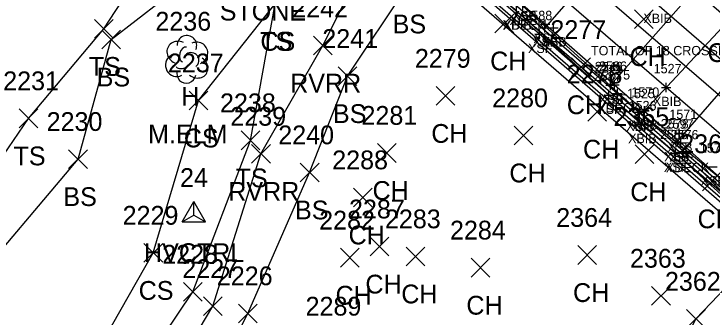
# Model space of a CAD drawing. Extents: x 1459992 to 1461532, y 647785 to 648535.
# Drawn here: x 1461256.6 to 1461331.1, y 648158.1 to 648190.4 of the extents above; entities that cross this region are included whole.
import ezdxf

# ---------------------------------------------------------------- set-up
doc = ezdxf.new("R2010")
doc.units = 0
for name, color, linetype in [('B_A', 7, 'Continuous'), ('B_C', 7, 'Continuous'), ('B_I', 7, 'Continuous'), ('B_TIC', 7, 'Continuous'), ('BB', 7, 'Continuous'), ('BDEFAULT', 7, 'Continuous'), ('BELB', 7, 'Continuous'), ('C_A', 7, 'Continuous'), ('C_I', 7, 'Continuous'), ('CPSM', 7, 'Continuous'), ('L_A', 7, 'Continuous'), ('L_C', 7, 'Continuous'), ('L_I', 7, 'Continuous'), ('L_TIC', 7, 'Continuous'), ('LAWE', 7, 'Continuous'), ('LELB', 7, 'Continuous'), ('LTD', 7, 'Continuous')]:
    doc.layers.add(name, color=color, linetype=linetype)

msp = doc.modelspace()

# ---------------------------------------------------------------- linework, layer by layer
at = {"layer": 'B_TIC'}
for p, q in [((1461313.281, 648189.283), (1461313.356, 648189.283)), ((1461313.247, 648188.887), (1461313.322, 648188.887)), ((1461314.158, 648188.899), (1461314.233, 648188.899)), ((1461312.687, 648188.203), (1461312.762, 648188.203)), ((1461320.233, 648182.764), (1461320.308, 648182.764)), ((1461320.683, 648182.814), (1461320.759, 648182.814)), ((1461326.197, 648182.545), (1461326.272, 648182.545)), ((1461320.992, 648181.882), (1461321.067, 648181.882)), ((1461320.086, 648181.72), (1461320.161, 648181.72)), ((1461323.356, 648179.892), (1461323.432, 648179.892)), ((1461323.863, 648180.043), (1461323.938, 648180.043)), ((1461323.551, 648178.602), (1461323.627, 648178.602)), ((1461327.584, 648177.68), (1461327.66, 648177.68)), ((1461327.237, 648176.673), (1461327.312, 648176.673)), ((1461327.752, 648176.637), (1461327.827, 648176.637)), ((1461327.176, 648175.537), (1461327.252, 648175.537)), ((1461328.315, 648175.511), (1461328.391, 648175.511))]:
    msp.add_line(p, q, dxfattribs=at)
for points in [[(1461310.231, 648190.193), (1461310.231, 648191.193)], [(1461310.883, 648190.176), (1461310.883, 648191.176)], [(1461312.777, 648189.283), (1461313.777, 648189.283)], [(1461313.243, 648188.387), (1461313.243, 648189.387)], [(1461313.277, 648188.783), (1461313.277, 648189.783)], [(1461314.154, 648188.399), (1461314.154, 648189.399)], [(1461312.683, 648187.703), (1461312.683, 648188.703)], [(1461312.743, 648188.887), (1461313.743, 648188.887)], [(1461313.654, 648188.899), (1461314.654, 648188.899)], [(1461312.183, 648188.203), (1461313.183, 648188.203)], [(1461320.229, 648182.264), (1461320.229, 648183.264)], [(1461320.68, 648182.314), (1461320.68, 648183.314)], [(1461319.729, 648182.764), (1461320.729, 648182.764)], [(1461320.18, 648182.814), (1461321.18, 648182.814)], [(1461325.694, 648182.545), (1461326.694, 648182.545)], [(1461326.194, 648182.045), (1461326.194, 648183.045)], [(1461320.082, 648181.22), (1461320.082, 648182.22)], [(1461320.488, 648181.882), (1461321.488, 648181.882)], [(1461320.988, 648181.382), (1461320.988, 648182.382)], [(1461319.582, 648181.72), (1461320.582, 648181.72)], [(1461323.353, 648179.392), (1461323.353, 648180.392)], [(1461323.859, 648179.543), (1461323.859, 648180.543)], [(1461322.853, 648179.892), (1461323.853, 648179.892)], [(1461323.359, 648180.043), (1461324.359, 648180.043)], [(1461323.548, 648178.102), (1461323.548, 648179.102)], [(1461323.048, 648178.602), (1461324.048, 648178.602)], [(1461327.581, 648177.18), (1461327.581, 648178.18)], [(1461327.081, 648177.68), (1461328.081, 648177.68)], [(1461326.733, 648176.673), (1461327.733, 648176.673)], [(1461327.233, 648176.173), (1461327.233, 648177.173)], [(1461327.248, 648176.637), (1461328.248, 648176.637)], [(1461327.748, 648176.137), (1461327.748, 648177.137)], [(1461327.173, 648175.037), (1461327.173, 648176.037)], [(1461328.312, 648175.011), (1461328.312, 648176.011)], [(1461326.673, 648175.537), (1461327.673, 648175.537)], [(1461327.812, 648175.511), (1461328.812, 648175.511)], [(1461330.62, 648174.098), (1461331.62, 648174.098)]]:
    msp.add_lwpolyline(points, dxfattribs=at)
at = {"layer": 'BB'}
for points in [[(1461357.803, 648164.521), (1461346.033, 648173.409), (1461325.183, 648191.393), (1461321.182, 648194.832), (1461311.295, 648203.276), (1461301.649, 648211.621), (1461295.127, 648216.651)], [(1461285.13, 648212.323), (1461354.607, 648152.433)], [(1461353.847, 648159.998), (1461342.222, 648168.764), (1461326.194, 648182.545), (1461313.236, 648193.724), (1461305.462, 648200.447), (1461296.007, 648208.646)], [(1461344.989, 648161.367), (1461336.505, 648169.128), (1461323.353, 648179.892), (1461310.889, 648191.178), (1461301.256, 648198.966), (1461293.739, 648205.641), (1461291.431, 648207.823)], [(1461344.755, 648160.272), (1461335.81, 648168.189), (1461323.548, 648178.602), (1461310.231, 648190.693), (1461300.415, 648198.699), (1461293.114, 648204.901), (1461290.791, 648207.096)], [(1461322.069, 648198.982), (1461313.243, 648188.887)], [(1461320.229, 648182.764), (1461329.099, 648192.816)], [(1461323.859, 648180.043), (1461332.641, 648189.458)], [(1461336.035, 648186.774), (1461327.233, 648176.673)]]:
    msp.add_lwpolyline(points, dxfattribs=at)
at = {"layer": 'BDEFAULT'}
for points in [[(1461360.363, 648157.144), (1461288.944, 648218.654)], [(1461354.171, 648150.001), (1461282.953, 648211.596)], [(1461353.858, 648151.867), (1461350.867, 648153.898), (1461289.362, 648207.393), (1461287.217, 648209.127), (1461285.016, 648211.458)], [(1461353.858, 648151.867), (1461285.016, 648211.458)], [(1461350.543, 648155.26), (1461340.882, 648163.524), (1461333.523, 648169.773), (1461327.173, 648175.537), (1461320.082, 648181.72), (1461312.683, 648188.203), (1461305.743, 648194.222), (1461298.88, 648200.08), (1461289.091, 648208.417)], [(1461292.894, 648206.723), (1461299.511, 648201.164), (1461306.374, 648195.289), (1461313.277, 648189.283), (1461320.68, 648182.814), (1461327.748, 648176.637), (1461334.696, 648170.496), (1461341.563, 648164.557), (1461348.45, 648158.681)]]:
    msp.add_lwpolyline(points, dxfattribs=at)
at = {"layer": 'BELB'}
msp.add_lwpolyline([(1461362.021, 648164.506), (1461356.918, 648168.766), (1461356.744, 648168.633), (1461346.243, 648178.153), (1461335.102, 648187.79), (1461324.925, 648196.655), (1461312.315, 648207.599), (1461296.583, 648221.232), (1461287.57, 648210.913), (1461301.391, 648198.959), (1461310.883, 648190.676), (1461320.988, 648181.882), (1461328.312, 648175.511), (1461338.631, 648166.593)], dxfattribs=at)
at = {"layer": 'CPSM'}
for p, q in [((1461274.537, 648168.22), (1461275.787, 648170.386)), ((1461277.037, 648168.22), (1461275.787, 648170.386)), ((1461275.788, 648168.942), (1461275.787, 648170.386)), ((1461274.537, 648168.22), (1461275.788, 648168.942)), ((1461275.788, 648168.942), (1461275.788, 648168.942)), ((1461275.788, 648168.942), (1461277.037, 648168.22)), ((1461274.537, 648168.22), (1461277.037, 648168.22))]:
    msp.add_line(p, q, dxfattribs=at)
at = {"layer": 'L_TIC'}
for points in [[(1461322.786, 648188.818), (1461324.786, 648190.818)], [(1461324.786, 648188.818), (1461322.786, 648190.818)], [(1461307.915, 648188.354), (1461309.915, 648190.354)], [(1461309.915, 648188.354), (1461307.915, 648190.354)], [(1461265.186, 648187.777), (1461267.186, 648189.777)], [(1461267.186, 648187.777), (1461265.186, 648189.777)], [(1461265.99, 648186.645), (1461267.99, 648188.645)], [(1461267.99, 648186.645), (1461265.99, 648188.645)], [(1461288.558, 648185.996), (1461290.558, 648187.996)], [(1461290.558, 648185.996), (1461288.558, 648187.996)], [(1461316.092, 648183.694), (1461318.092, 648185.694)], [(1461318.092, 648183.694), (1461316.092, 648185.694)], [(1461291.193, 648182.75), (1461293.193, 648184.75)], [(1461293.193, 648182.75), (1461291.193, 648184.75)], [(1461301.64, 648180.64), (1461303.64, 648182.64)], [(1461303.64, 648180.64), (1461301.64, 648182.64)], [(1461275.289, 648180.15), (1461277.289, 648182.15)], [(1461277.289, 648180.15), (1461275.289, 648182.15)], [(1461317.822, 648178.961), (1461319.822, 648180.961)], [(1461319.822, 648178.961), (1461317.822, 648180.961)], [(1461257.154, 648178.244), (1461259.154, 648180.244)], [(1461259.154, 648178.244), (1461257.154, 648180.244)], [(1461309.967, 648176.427), (1461311.967, 648178.427)], [(1461311.967, 648176.427), (1461309.967, 648178.427)], [(1461280.846, 648175.9), (1461282.846, 648177.9)], [(1461282.846, 648175.9), (1461280.846, 648177.9)], [(1461295.371, 648174.562), (1461297.371, 648176.562)], [(1461297.371, 648174.562), (1461295.371, 648176.562)], [(1461262.44, 648173.908), (1461264.44, 648175.908)], [(1461264.44, 648173.908), (1461262.44, 648175.908)], [(1461281.957, 648174.462), (1461283.957, 648176.462)], [(1461283.957, 648174.462), (1461281.957, 648176.462)], [(1461322.866, 648174.422), (1461324.866, 648176.422)], [(1461324.866, 648174.422), (1461322.866, 648176.422)], [(1461287.148, 648172.487), (1461289.148, 648174.487)], [(1461289.148, 648172.487), (1461287.148, 648174.487)], [(1461330.042, 648171.541), (1461332.042, 648173.541)], [(1461332.042, 648171.541), (1461330.042, 648173.541)], [(1461292.817, 648169.822), (1461294.817, 648171.822)], [(1461294.817, 648169.822), (1461292.817, 648171.822)], [(1461294.61, 648164.59), (1461296.61, 648166.59)], [(1461296.61, 648164.59), (1461294.61, 648166.59)], [(1461270.471, 648163.918), (1461272.471, 648165.918)], [(1461272.471, 648163.918), (1461270.471, 648165.918)], [(1461291.423, 648163.407), (1461293.423, 648165.407)], [(1461293.423, 648163.407), (1461291.423, 648165.407)], [(1461298.439, 648163.54), (1461300.439, 648165.54)], [(1461300.439, 648163.54), (1461298.439, 648165.54)], [(1461316.757, 648163.688), (1461318.757, 648165.688)], [(1461318.757, 648163.688), (1461316.757, 648165.688)], [(1461305.38, 648162.342), (1461307.38, 648164.342)], [(1461307.38, 648162.342), (1461305.38, 648164.342)], [(1461274.686, 648159.772), (1461276.686, 648161.772)], [(1461276.686, 648159.772), (1461274.686, 648161.772)], [(1461324.629, 648159.341), (1461326.629, 648161.341)], [(1461326.629, 648159.341), (1461324.629, 648161.341)], [(1461276.829, 648158.24), (1461278.829, 648160.24)], [(1461278.829, 648158.24), (1461276.829, 648160.24)], [(1461280.565, 648157.473), (1461282.565, 648159.473)], [(1461282.565, 648157.473), (1461280.565, 648159.473)], [(1461328.36, 648156.887), (1461330.36, 648158.887)], [(1461330.36, 648156.887), (1461328.36, 648158.887)]]:
    msp.add_lwpolyline(points, dxfattribs=at)
at = {"layer": 'LAWE'}
msp.add_lwpolyline([(1461175.582, 648047.692), (1461190.072, 648060.795), (1461210.579, 648076.7), (1461225.386, 648087.992), (1461242.999, 648102.806), (1461257.751, 648117.016), (1461268.272, 648143.142), (1461277.829, 648159.24), (1461282.957, 648175.462), (1461289.558, 648186.996), (1461293.87, 648195.588), (1461292.337, 648203.444)], dxfattribs=at)
at = {"layer": 'LELB'}
for points in [[(1461216.735, 648025.379), (1461232.531, 648043.682), (1461249.111, 648052.696), (1461265.41, 648068.573), (1461273.176, 648074.771), (1461285.769, 648090.042), (1461304.003, 648110.191), (1461314.102, 648129.874), (1461321.787, 648141.876), (1461329.36, 648157.887), (1461338.075, 648167.022), (1461343.94, 648182.363), (1461347.487, 648202.693), (1461348.844, 648222.98), (1461349.522, 648245.94), (1461349.946, 648262.877), (1461353.497, 648277.365), (1461366.77, 648299.226), (1461380.277, 648319.065), (1461391.623, 648332.953), (1461418.599, 648338.961), (1461441.306, 648340.652), (1461465.695, 648340.733), (1461485.923, 648346.235)], [(1461181.212, 648043.592), (1461191.79, 648059.054), (1461212.855, 648073.874), (1461227.371, 648085.596), (1461246.178, 648099.024), (1461260.669, 648114.058), (1461272.144, 648139.82), (1461281.565, 648158.473), (1461288.148, 648173.487), (1461292.193, 648183.75), (1461298.563, 648193.295), (1461300.86, 648204.122), (1461298.63, 648210.737)], [(1461127.841, 648072.025), (1461157.366, 648076.315), (1461166.908, 648084.021), (1461183.556, 648102.817), (1461209.905, 648116.903), (1461222.502, 648127.212), (1461235.952, 648145.681), (1461248.534, 648165.182), (1461258.154, 648179.244), (1461266.186, 648188.777), (1461271.994, 648197.654)], [(1461133.589, 648067.118), (1461157.379, 648067.438), (1461176.46, 648078.839), (1461190.117, 648095.99), (1461212.044, 648111.684), (1461225.88, 648123.016), (1461241.312, 648138.966), (1461251.31, 648160.567), (1461263.44, 648174.908), (1461266.99, 648187.645), (1461277.642, 648195.929)], [(1461171.661, 648050.372), (1461189.066, 648062.585), (1461207.829, 648079.497), (1461223.93, 648090.745), (1461240.199, 648105.174), (1461254.637, 648120.348), (1461266.382, 648146.936), (1461275.686, 648160.772), (1461281.846, 648176.9), (1461284.459, 648191.448), (1461287.846, 648196.16)], [(1461162.415, 648057.492), (1461184.81, 648068.652), (1461202.033, 648084.354), (1461220.873, 648096.789), (1461234.917, 648111.93), (1461250.129, 648125.473), (1461262.717, 648149.553), (1461271.471, 648164.918), (1461276.289, 648181.15), (1461284.459, 648191.448)]]:
    msp.add_lwpolyline(points, dxfattribs=at)
at = {"layer": 'LTD'}
msp.add_line((1461275.01, 648185.587), (1461275.01, 648185.587), dxfattribs=at)
msp.add_line((1461275.01, 648185.587), (1461275.01, 648185.587), dxfattribs=at)
msp.add_arc((1461275.057, 648187.021), 1.047, 335.52715, 180.95627, dxfattribs=at)
for centre, major_axis, ratio, start_param, end_param in [((1461274.218, 648186.254), (1.21, -0.512), 0.895232, 1.570796, 4.712389), ((1461276.052, 648186.171), (-1.141, -0.483), 0.949671, 1.570796, 4.712389), ((1461274.802, 648186.045), (-0.208, -0.792), 0.645439, 3.141593, 6.283185), ((1461275.51, 648185.42), (-0.5, 0.667), 0.989748, 3.141593, 6.283185), ((1461273.927, 648184.879), (0.584, -1.042), 0.959034, 3.141593, 6.283185), ((1461276.01, 648184.754), (-1.09, 0.792), 0.841452, 1.570796, 4.712389), ((1461274.552, 648184.837), (-0.625, -0.083), 0.423636, 0, 3.141593), ((1461275.01, 648184.087), (0.265, 1.061), 0.942809, 1.570796, 4.712389)]:
    msp.add_ellipse(centre, major_axis=major_axis, ratio=ratio, start_param=start_param, end_param=end_param, dxfattribs=at)

# ---------------------------------------------------------------- texts
at = {"layer": 'B_A'}
for s, p in [('XSB', (1461309.705, 648189.688)), ('XBIB', (1461309.46, 648189.178)), ('XBIB', (1461323.754, 648189.393)), ('XDECK', (1461308.725, 648188.676)), ('XBIB', (1461308.802, 648188.693)), ('XSB', (1461311.979, 648186.887)), ('XSF', (1461312.037, 648187.283)), ('XSB', (1461312.891, 648186.899)), ('XSF', (1461311.443, 648186.203)), ('XSB', (1461318.965, 648180.764)), ('XSF', (1461319.44, 648180.814)), ('XBIB', (1461324.764, 648180.545)), ('XDECK', (1461318.831, 648179.882)), ('XSF', (1461318.842, 648179.72)), ('XBIB', (1461321.923, 648177.892)), ('XSB', (1461322.595, 648178.043)), ('XBIB', (1461322.119, 648176.602)), ('XSB', (1461326.317, 648175.68)), ('XSB', (1461325.97, 648174.673)), ('XSF', (1461326.508, 648174.637)), ('XSF', (1461325.932, 648173.537)), ('XDECK', (1461326.154, 648173.511)), ('XSB', (1461329.856, 648172.098))]:
    msp.add_text(s, height=1, dxfattribs=at).set_placement(p)
at = {"layer": 'B_C'}
msp.add_text('TOTAL OF 18 CROSSBEAM & WE WHAT', height=1, dxfattribs=at).set_placement((1461318.165, 648185.958))
at = {"layer": 'B_I'}
for s, p in [('2588', (1461311.054, 648189.703)), ('2546', (1461318.572, 648184.264)), ('2596', (1461319.022, 648184.314)), ('1527', (1461324.847, 648184.045)), ('2587', (1461318.452, 648183.22)), ('2575', (1461319.358, 648183.382)), ('1570', (1461322.469, 648181.543)), ('1525', (1461322.006, 648181.392)), ('1526', (1461322.174, 648180.102)), ('1571', (1461326.518, 648179.18)), ('2578', (1461325.604, 648178.173)), ('2597', (1461326.118, 648178.137)), ('2586', (1461325.515, 648177.037)), ('2576', (1461326.654, 648177.011)), ('1572', (1461329.773, 648175.598))]:
    msp.add_text(s, height=1, dxfattribs=at).set_placement(p)
at = {"layer": 'C_A'}
msp.add_text('HVCTRL', height=2, dxfattribs=at).set_placement((1461270.481, 648163.942))
at = {"layer": 'C_I'}
msp.add_text('24', height=2, dxfattribs=at).set_placement((1461274.323, 648171.942))
at = {"layer": 'L_A'}
for s, p in [('STONE', (1461278.557, 648189.668)), ('BS', (1461297.004, 648188.295)), ('TS', (1461282.868, 648186.448)), ('CS', (1461282.899, 648186.448)), ('CH', (1461330.585, 648185.245)), ('CH', (1461307.403, 648184.354)), ('CH', (1461322.274, 648184.818)), ('TS', (1461264.596, 648183.777)), ('BS', (1461265.431, 648182.645)), ('RVRR', (1461286.069, 648181.996)), ('H', (1461274.443, 648180.587)), ('CH', (1461315.58, 648179.694)), ('BS', (1461290.634, 648178.75)), ('CS', (1461274.73, 648176.15)), ('CH', (1461301.128, 648176.64)), ('CH', (1461317.311, 648174.961)), ('TS', (1461256.563, 648174.244)), ('CH', (1461309.455, 648172.427)), ('TS', (1461280.255, 648171.9)), ('RVRR', (1461279.469, 648170.462)), ('CH', (1461294.859, 648170.562)), ('CH', (1461322.354, 648170.422)), ('BS', (1461261.881, 648169.908)), ('BS', (1461286.589, 648168.487)), ('CH', (1461329.531, 648167.541)), ('CH', (1461292.305, 648165.822)), ('CH', (1461294.098, 648160.59)), ('CS', (1461269.912, 648159.918)), ('CH', (1461316.245, 648159.688)), ('CH', (1461290.912, 648159.407)), ('CH', (1461297.928, 648159.54)), ('CH', (1461304.868, 648158.342))]:
    msp.add_text(s, height=2, dxfattribs=at).set_placement(p)
at = {"layer": 'L_C'}
msp.add_text('M.ELM', height=2, dxfattribs=at).set_placement((1461270.916, 648176.587))
at = {"layer": 'L_I'}
for s, p in [('2242', (1461286.298, 648189.996)), ('2236', (1461271.695, 648188.587)), ('2277', (1461313.832, 648187.694)), ('2241', (1461289.5, 648186.75)), ('2279', (1461299.373, 648184.64)), ('2237', (1461273.029, 648184.15)), ('2278', (1461315.563, 648182.961)), ('2231', (1461255.461, 648182.244)), ('2238', (1461278.586, 648179.9)), ('2280', (1461307.621, 648180.427)), ('2239', (1461279.689, 648178.462)), ('2281', (1461293.678, 648178.562)), ('2365', (1461320.559, 648178.422)), ('2230', (1461260.094, 648177.908)), ('2240', (1461284.801, 648176.487)), ('2366', (1461327.68, 648175.541)), ('2288', (1461290.557, 648173.822)), ('2287', (1461292.35, 648168.59)), ('2229', (1461268.203, 648167.918)), ('2282', (1461289.163, 648167.407)), ('2283', (1461296.18, 648167.54)), ('2364', (1461314.45, 648167.688)), ('2284', (1461303.12, 648166.342)), ('2228', (1461272.426, 648163.772)), ('2363', (1461322.322, 648163.341)), ('2227', (1461274.57, 648162.24)), ('2226', (1461278.25, 648161.473)), ('2362', (1461326.052, 648160.887)), ('2289', (1461287.717, 648158.239))]:
    msp.add_text(s, height=2, dxfattribs=at).set_placement(p)

doc.saveas('drawing.dxf')
